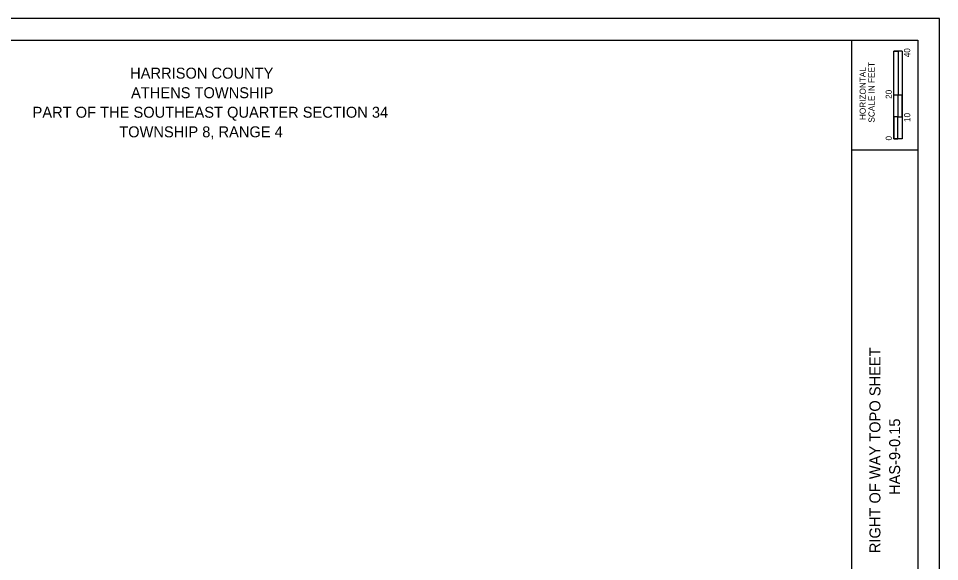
# Model space of a CAD drawing. Extents: x -1 to 34, y 0 to 22.
# Drawn here: x 12.97 to 34, y 9.59 to 22 of the extents above; entities that cross this region are included whole.
import ezdxf

# ---------------------------------------------------------------- set-up
doc = ezdxf.new("R2010")
doc.units = 0
for name, color, linetype in [('SH_Border', 7, 'Continuous'), ('SH_Cut_Line', 7, 'Continuous'), ('SH_Data', 7, 'Continuous')]:
    doc.layers.add(name, color=color, linetype=linetype)

msp = doc.modelspace()

# ---------------------------------------------------------------- linework, layer by layer
at = {"layer": 'SH_Border'}
for p, q in [((32, 0.5), (32, 21.5)), ((32, 19), (33.5, 19))]:
    msp.add_line(p, q, dxfattribs=at)
msp.add_lwpolyline([(1.5, 21.5), (33.5, 21.5), (33.5, 0.5), (1.5, 0.5)], close=True, dxfattribs=at)
at = {"layer": 'SH_Cut_Line'}
msp.add_lwpolyline([(0, 0), (34, 0), (34, 22), (0, 22)], close=True, dxfattribs=at)
at = {"layer": 'SH_Data'}
for p, q in [((32.957, 19.25), (32.957, 21.25)), ((33.144, 21.25), (32.957, 21.25)), ((32.957, 20.25), (32.957, 21.25)), ((32.957, 21.25), (33.05, 21.25)), ((33.05, 21.25), (33.051, 21.25)), ((33.051, 21.25), (33.051, 20.25)), ((33.144, 21.25), (33.144, 19.25)), ((33.051, 20.25), (32.957, 20.25)), ((33.143, 20.25), (33.05, 20.25)), ((33.05, 20.25), (33.05, 19.75)), ((33.143, 19.75), (33.143, 20.25)), ((33.05, 19.75), (32.957, 19.75)), ((32.957, 19.75), (32.957, 19.25)), ((33.05, 19.25), (33.05, 19.75)), ((33.05, 19.75), (33.143, 19.75)), ((33.144, 19.25), (32.957, 19.25)), ((32.957, 19.25), (33.05, 19.25))]:
    msp.add_line(p, q, dxfattribs=at)

# ---------------------------------------------------------------- texts
for s, height, p in [('40', 0.14, (33.33, 21.112)), ('HORIZONTAL', 0.14, (32.315, 19.679)), ('SCALE IN FEET', 0.14, (32.517, 19.621)), ('20', 0.14, (32.91, 20.162)), ('10', 0.14, (33.33, 19.633)), ('0', 0.14, (32.91, 19.211)), ('RIGHT OF WAY TOPO SHEET', 0.25, (32.65, 9.787)), ('HAS-9-0.15', 0.25, (33.1, 11.115))]:
    msp.add_text(s, height=height, rotation=90, dxfattribs=at).set_placement(p)
for s, p in [('HARRISON COUNTY', (15.523, 20.625)), ('ATHENS TOWNSHIP', (15.544, 20.178)), ('PART OF THE SOUTHEAST QUARTER SECTION 34', (13.296, 19.732)), ('TOWNSHIP 8, RANGE 4', (15.274, 19.285))]:
    msp.add_text(s, height=0.25, dxfattribs=at).set_placement(p)

doc.saveas('drawing.dxf')
